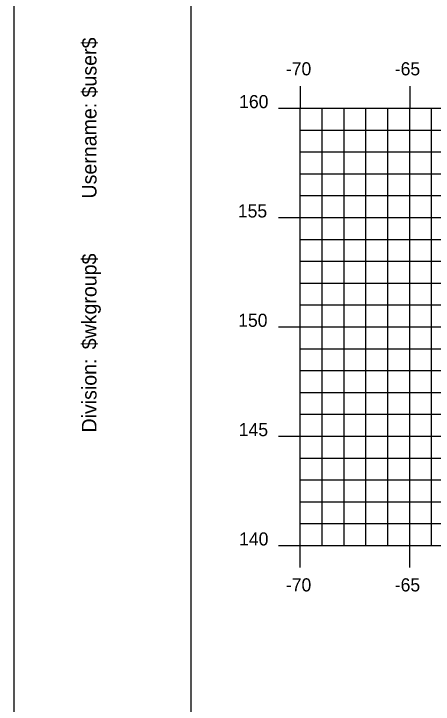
# Model space of a CAD drawing. Extents: x 1147855 to 1148025, y 608981 to 609091.
# Drawn here: x 1147855.12 to 1147874.28, y 609013.08 to 609044.65 of the extents above; entities that cross this region are included whole.
import ezdxf

# ---------------------------------------------------------------- set-up
doc = ezdxf.new("R2010")
doc.units = 0
for name, color, linetype in [('BORDER', 7, 'Continuous'), ('H_V ANNOTATION', 7, 'Continuous'), ('MAJOR', 7, 'Continuous'), ('MINOR', 7, 'Continuous'), ('PLOT BOUNDARY', 7, 'Continuous')]:
    doc.layers.add(name, color=color, linetype=linetype)

msp = doc.modelspace()

# ---------------------------------------------------------------- linework, layer by layer
at = {"layer": 'BORDER'}
msp.add_lwpolyline([(1147863.211, 608984.335), (1148023.211, 608984.335), (1148023.211, 609089.335), (1147863.211, 609089.335)], close=True, dxfattribs=at)
at = {"layer": 'MAJOR'}
for p, q in [((1147868.211, 609041.337), (1147868.211, 609040.335)), ((1147873.211, 609041.337), (1147873.211, 609040.335)), ((1147867.209, 609040.335), (1147868.211, 609040.335)), ((1147868.211, 609040.335), (1148008.211, 609040.335)), ((1147868.211, 609020.335), (1147868.211, 609040.335)), ((1147868.211, 609020.335), (1147868.211, 609040.335)), ((1147868.211, 609040.335), (1148008.211, 609040.335)), ((1147873.211, 609020.335), (1147873.211, 609040.335)), ((1147867.209, 609035.335), (1147868.211, 609035.335)), ((1147868.211, 609035.335), (1148008.211, 609035.335)), ((1147867.209, 609030.335), (1147868.211, 609030.335)), ((1147868.211, 609030.335), (1148008.211, 609030.335)), ((1147867.209, 609025.335), (1147868.211, 609025.335)), ((1147868.211, 609025.335), (1148008.211, 609025.335)), ((1147867.209, 609020.335), (1147868.211, 609020.335)), ((1147868.211, 609020.335), (1148008.211, 609020.335)), ((1147868.211, 609020.335), (1148008.211, 609020.335)), ((1147868.211, 609019.333), (1147868.211, 609020.335)), ((1147873.211, 609019.333), (1147873.211, 609020.335))]:
    msp.add_line(p, q, dxfattribs=at)
at = {"layer": 'MINOR'}
for p, q in [((1147869.211, 609020.335), (1147869.211, 609040.335)), ((1147870.211, 609020.335), (1147870.211, 609040.335)), ((1147871.211, 609020.335), (1147871.211, 609040.335)), ((1147872.211, 609020.335), (1147872.211, 609040.335)), ((1147874.211, 609020.335), (1147874.211, 609040.335)), ((1147868.211, 609039.335), (1148008.211, 609039.335)), ((1147868.211, 609039.335), (1147869.213, 609039.335)), ((1147868.211, 609038.335), (1148008.211, 609038.335)), ((1147868.211, 609038.335), (1147869.213, 609038.335)), ((1147868.211, 609037.335), (1148008.211, 609037.335)), ((1147868.211, 609037.335), (1147869.213, 609037.335)), ((1147868.211, 609036.335), (1148008.211, 609036.335)), ((1147868.211, 609036.335), (1147869.213, 609036.335)), ((1147868.211, 609034.335), (1148008.211, 609034.335)), ((1147868.211, 609034.335), (1147869.213, 609034.335)), ((1147868.211, 609033.335), (1148008.211, 609033.335)), ((1147868.211, 609033.335), (1147869.213, 609033.335)), ((1147868.211, 609032.335), (1148008.211, 609032.335)), ((1147868.211, 609032.335), (1147869.213, 609032.335)), ((1147868.211, 609031.335), (1148008.211, 609031.335)), ((1147868.211, 609031.335), (1147869.213, 609031.335)), ((1147868.211, 609029.335), (1148008.211, 609029.335)), ((1147868.211, 609029.335), (1147869.213, 609029.335)), ((1147868.211, 609028.335), (1148008.211, 609028.335)), ((1147868.211, 609028.335), (1147869.213, 609028.335)), ((1147868.211, 609027.335), (1148008.211, 609027.335)), ((1147868.211, 609027.335), (1147869.213, 609027.335)), ((1147868.211, 609026.335), (1148008.211, 609026.335)), ((1147868.211, 609026.335), (1147869.213, 609026.335)), ((1147868.211, 609024.335), (1148008.211, 609024.335)), ((1147868.211, 609024.335), (1147869.213, 609024.335)), ((1147868.211, 609023.335), (1148008.211, 609023.335)), ((1147868.211, 609023.335), (1147869.213, 609023.335)), ((1147868.211, 609022.335), (1148008.211, 609022.335)), ((1147868.211, 609022.335), (1147869.213, 609022.335)), ((1147868.211, 609021.335), (1148008.211, 609021.335)), ((1147868.211, 609021.335), (1147869.213, 609021.335))]:
    msp.add_line(p, q, dxfattribs=at)
at = {"layer": 'PLOT BOUNDARY'}
msp.add_lwpolyline([(1147855.117, 608981.276), (1148025.117, 608981.276), (1148025.117, 609091.276), (1147855.117, 609091.276)], close=True, dxfattribs=at)

# ---------------------------------------------------------------- texts
at = {"layer": 'BORDER'}
for s, p in [('$user$', (1147858.896, 609040.827)), ('Username:', (1147858.896, 609036.203)), ('$wkgroup$', (1147858.896, 609029.305)), ('Division:', (1147858.896, 609025.501))]:
    msp.add_text(s, height=0.6696, rotation=90, dxfattribs=at).set_placement(p)
at = {"layer": 'H_V ANNOTATION'}
for s, p in [('-70', (1147867.552, 609041.835)), ('-65', (1147872.528, 609041.835)), ('160', (1147865.415, 609040.335)), ('155', (1147865.356, 609035.335)), ('150', (1147865.372, 609030.335)), ('145', (1147865.399, 609025.335)), ('140', (1147865.415, 609020.335)), ('-70', (1147867.552, 609018.235)), ('-65', (1147872.528, 609018.235))]:
    msp.add_text(s, height=0.6, dxfattribs=at).set_placement(p)
at = {"layer": 'MAJOR'}
msp.add_text('-', height=0.006, dxfattribs=at).set_placement((1147868.206, 609020.335))

doc.saveas('drawing.dxf')
